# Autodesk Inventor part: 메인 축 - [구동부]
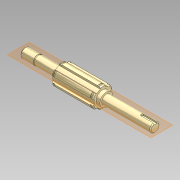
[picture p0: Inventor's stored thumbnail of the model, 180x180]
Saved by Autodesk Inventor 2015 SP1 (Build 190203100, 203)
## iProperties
Company: 한국ATC센터
Created: 2014-07
Part Number: 메인 축 - [구동부]
Document SubType Name: 모델링
Designer: KYOUNG IL JANG
Mass: 168.352 g
Surface Area: 72.5104 cm^2
Volume: 21.4461 cm^3
Density: 7.85 g/cm^3
Material: 강철, 연강
Appearance: 반연마
변환 표준: STEP AP214IS
파일 이름: C:\Users\SeoGD\Desktop\?쒗뿕\硫붿씤 異?.stp
전처리기: Build: 253, Release: 2010 SP1 - Date: Wed 07/29/2009
전송 단위: 밀리미터
불확실성: 0.01
Author: KYOUNG IL JANG
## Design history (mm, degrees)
sketch "스케치1"
  geometry: L1 (-69.5, 0)-(69.5, 0); L2 (69.5, 0)-(69.5, 5); L3 (69.5, 5)-(55.5, 5); L4 (55.5, 5)-(55.5, 4.8); L5 (55.5, 4.8)-(54.35, 4.8); L6 (54.35, 4.8)-(54.35, 5); L7 (54.35, 5)-(30.5, 5); L8 (30.5, 5)-(30.5, 9); L9 (30.5, 9)-(-13.5, 9); L10 (-13.5, 9)-(-13.5, 7); L11 (-13.5, 7)-(-17.5, 7); L12 (-17.5, 7)-(-17.5, 5); L13 (-17.5, 5)-(-69.5, 5); L14 (-69.5, 5)-(-69.5, 0); 2 further points
  constraints: 28 end point, 9 parallel, 4 collinear, 2 perpendicular, 1 coincident, 1 horizontal, 1 midpoint
  dimensions: "d2" = 1.15 distance between parallel lines of L6 L4; "d3" = 10 diameter of L3 L1; "d4" = 9.6 diameter of L5 L1; "d6" = 44 distance between parallel lines of L10 L8; "d7" = 4 distance between parallel lines of L12 L10; "d8" = 14 diameter of L11 L1; "d9" = 18 diameter of L9 L1; "d33" = 52 distance from line of L12.end L14; "d37" = 39 distance between parallel lines of L8 L2; "d38" = 14 distance between parallel lines of L2 L4
revolve "회전1" sketch "스케치1" stored, may be unused: angle "d10" = 90 deg
sketch "스케치2"
  geometry: L1 (2.5, 10.712)-(2.5, 8.646); L2 (-2.5, 10.712)-(-2.5, 8.646); A1 r 9 centre (0, 0) between (2.5, 8.646) and (-2.5, 8.646) reference; A2 r 11 centre (0, 0) between (2.5, 10.712) and (-2.5, 10.712); 1 further point
  constraints: 4 end point, 4 point on circle, 2 parallel, 1 centre point, 1 coincident, 1 vertical
  dimensions: "d11" = 22 diameter of A2; "d12" = 5 distance between parallel lines of L1 L2
extrude "돌출1" join sketch "스케치2" stored distance "d13" = 10; taper "d14" = 0 deg
chamfer "모따기1" distance "d15" = 1; stored, may be unused: second distance "d16" = 2, angle "d17" = 45 deg
node "작업 평면1"
node "작업 평면2"
sketch "스케치3"
  geometry: L1 (2.5, 10.712)-(2.5, 10.198); L2 (-2.5, 10.712)-(-2.5, 10.198); A1 r 11 centre (0, 0) between (2.5, 10.712) and (-2.5, 10.712) reference; A2 r 10.5 centre (0, 0) between (2.5, 10.198) and (-2.5, 10.198); 1 further point
  constraints: 4 end point, 2 point on circle, 1 centre point, 1 coincident, 1 parallel, 1 vertical
  dimensions: "d19" = 21 diameter of A2
extrude "돌출2" cut sketch "스케치3" distance "d20" = 1.35; taper "d21" = 0 deg
node "작업 평면3"
sketch "스케치4"
  geometry: L1 (-26, -5)-(-26, 5) reference; L2 (-26, 1.5)-(-12.5, 1.5); L3 (-12.5, -1.5)-(-26, -1.5); A1 r 1.5 centre (-12.5, 0) between (-12.5, -1.5) and (-12.5, 1.5); 2 further points
  constraints: 4 end point, 2 perpendicular, 2 point on circle, 2 point on line, 2 tangent, 1 centre point, 1 horizontal alignment, 1 midpoint
  dimensions: "d25" = 3 distance between parallel lines of L3 L2; "d26" = 15 dimension on A1 L1
extrude "돌출3" cut sketch "스케치4" distance "d27" = 1.8; taper "d28" = 0 deg
chamfer "모따기2" distance "d29" = 1; stored, may be unused: second distance "d30" = 2, angle "d31" = 45 deg
node "솔리드1"
node "솔리드 본체"
node "곡면 본체"
mirror "대칭1"
pattern_circular "원형 패턴1" dims "d23" = 360 deg
node "솔리드2"
other parameters: "d18" = -1.65
